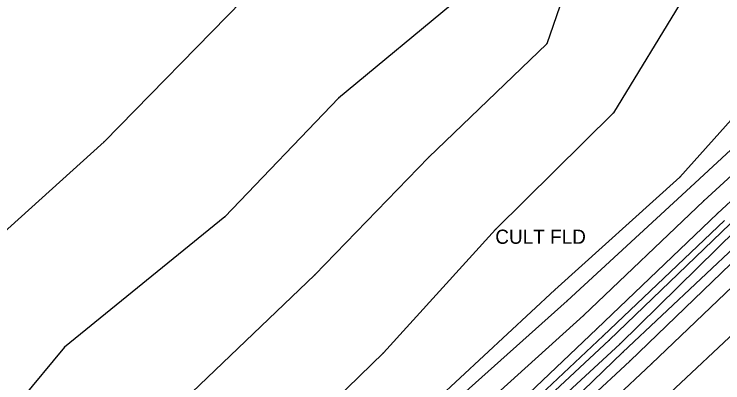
# Model space of a CAD drawing. Extents: x 1419505 to 1434054, y 1956910 to 1968644.
# Drawn here: x 1433605.5 to 1433855.4, y 1968338.4 to 1968468.2 of the extents above; entities that cross this region are included whole.
import ezdxf

# ---------------------------------------------------------------- set-up
doc = ezdxf.new("R2010")
doc.units = 0
for name, color, linetype in [('S_BREAKLINE', 7, 'Continuous'), ('S_DITCHLINE', 7, 'Continuous'), ('S_EDGE_PAVEMENT', 7, 'Continuous'), ('S_GRD_PT_SYM', 7, 'Continuous'), ('S_MSC_PT_SYM', 7, 'Continuous'), ('S_PAVEMENT_CROWN', 7, 'Continuous'), ('S_RDW_PT_SYM', 7, 'Continuous'), ('S_SHOULDER', 7, 'Continuous'), ('S_SURVEY_TEXT_ANNOT', 7, 'Continuous')]:
    doc.layers.add(name, color=color, linetype=linetype)

msp = doc.modelspace()

# ---------------------------------------------------------------- linework, layer by layer
at = {"layer": 'S_BREAKLINE'}
for p, q in [((1433813.2202, 1968515.1117), (1433793.2969, 1968457.802)), ((1433769.5064, 1968479.7105), (1433719.8082, 1968438.6018)), ((1433844.6113, 1968479.0114), (1433816.8765, 1968433.4835)), ((1433686.009, 1968473.093), (1433637.1959, 1968423.2958)), ((1433793.2969, 1968457.802), (1433751.5592, 1968417.7324)), ((1433870.993, 1968445.1822), (1433840.22, 1968410.773)), ((1433719.8082, 1968438.6018), (1433679.7596, 1968396.7851)), ((1433875.4372, 1968436.4227), (1433843.9742, 1968407.2728)), ((1433816.8765, 1968433.4835), (1433775.1918, 1968392.3258)), ((1433880.9386, 1968432.1494), (1433848.6865, 1968402.4875)), ((1433888.9011, 1968430.7533), (1433853.5108, 1968398.0462)), ((1433637.1959, 1968423.2958), (1433588.7407, 1968379.547)), ((1433751.5592, 1968417.7324), (1433711.5347, 1968376.4368)), ((1433840.22, 1968410.773), (1433796.2231, 1968371.1104)), ((1433843.9742, 1968407.2728), (1433800.5664, 1968367.2802)), ((1433848.6865, 1968402.4875), (1433806.3228, 1968362.0569)), ((1433679.7596, 1968396.7851), (1433623.2, 1968350.9581)), ((1433853.5108, 1968398.0462), (1433810.9331, 1968357.3636)), ((1433775.1918, 1968392.3258), (1433735.7682, 1968348.972)), ((1433860.1253, 1968392.2618), (1433819.0836, 1968352.0172)), ((1433862.7984, 1968389.2636), (1433820.1957, 1968349.097)), ((1433711.5347, 1968376.4368), (1433655.7821, 1968323.1873)), ((1433796.2231, 1968371.1104), (1433754.1524, 1968332.1799)), ((1433800.5664, 1968367.2802), (1433757.7176, 1968329.0797)), ((1433806.3228, 1968362.0569), (1433763.508, 1968323.4934)), ((1433810.9331, 1968357.3636), (1433769.0694, 1968317.559)), ((1433819.0836, 1968352.0172), (1433774.8767, 1968311.2866)), ((1433623.2, 1968350.9581), (1433583.6564, 1968303.4301)), ((1433735.7682, 1968348.972), (1433684.6589, 1968299.4658)), ((1433820.1957, 1968349.097), (1433777.9199, 1968308.5754))]:
    msp.add_line(p, q, dxfattribs=at)
at = {"layer": 'S_DITCHLINE'}
for p, q in [((1433855.973, 1968395.581), (1433813.2462, 1968354.9544)), ((1433858.0051, 1968394.3679), (1433815.3694, 1968353.3243)), ((1433813.2462, 1968354.9544), (1433771.0385, 1968315.3208)), ((1433815.3694, 1968353.3243), (1433773.3496, 1968314.4268))]:
    msp.add_line(p, q, dxfattribs=at)
at = {"layer": 'S_EDGE_PAVEMENT'}
for p, q in [((1433869.5289, 1968382.5402), (1433830.2483, 1968344.9908)), ((1433830.2483, 1968344.9908), (1433784.2344, 1968301.986))]:
    msp.add_line(p, q, dxfattribs=at)
at = {"layer": 'S_GRD_PT_SYM'}
for points in [[(1433793.2969, 1968457.802), (1433793.2969, 1968457.852), (1433793.2969, 1968457.802), (1433793.2469, 1968457.802), (1433793.2969, 1968457.802), (1433793.2969, 1968457.752), (1433793.2969, 1968457.802), (1433793.3469, 1968457.802)], [(1433719.8082, 1968438.6018), (1433719.8082, 1968438.6518), (1433719.8082, 1968438.6018), (1433719.7582, 1968438.6018), (1433719.8082, 1968438.6018), (1433719.8082, 1968438.5518), (1433719.8082, 1968438.6018), (1433719.8582, 1968438.6018)], [(1433816.8765, 1968433.4835), (1433816.8765, 1968433.5335), (1433816.8765, 1968433.4835), (1433816.8265, 1968433.4835), (1433816.8765, 1968433.4835), (1433816.8765, 1968433.4335), (1433816.8765, 1968433.4835), (1433816.9265, 1968433.4835)], [(1433637.1959, 1968423.2958), (1433637.1959, 1968423.3458), (1433637.1959, 1968423.2958), (1433637.1459, 1968423.2958), (1433637.1959, 1968423.2958), (1433637.1959, 1968423.2458), (1433637.1959, 1968423.2958), (1433637.2459, 1968423.2958)], [(1433751.5592, 1968417.7324), (1433751.5592, 1968417.7824), (1433751.5592, 1968417.7324), (1433751.5092, 1968417.7324), (1433751.5592, 1968417.7324), (1433751.5592, 1968417.6824), (1433751.5592, 1968417.7324), (1433751.6092, 1968417.7324)], [(1433840.22, 1968410.773), (1433840.22, 1968410.823), (1433840.22, 1968410.773), (1433840.17, 1968410.773), (1433840.22, 1968410.773), (1433840.22, 1968410.723), (1433840.22, 1968410.773), (1433840.27, 1968410.773)], [(1433843.9742, 1968407.2728), (1433843.9742, 1968407.3228), (1433843.9742, 1968407.2728), (1433843.9242, 1968407.2728), (1433843.9742, 1968407.2728), (1433843.9742, 1968407.2228), (1433843.9742, 1968407.2728), (1433844.0242, 1968407.2728)], [(1433848.6865, 1968402.4875), (1433848.6865, 1968402.5375), (1433848.6865, 1968402.4875), (1433848.6365, 1968402.4875), (1433848.6865, 1968402.4875), (1433848.6865, 1968402.4375), (1433848.6865, 1968402.4875), (1433848.7365, 1968402.4875)], [(1433679.7596, 1968396.7851), (1433679.7596, 1968396.8351), (1433679.7596, 1968396.7851), (1433679.7096, 1968396.7851), (1433679.7596, 1968396.7851), (1433679.7596, 1968396.7351), (1433679.7596, 1968396.7851), (1433679.8096, 1968396.7851)], [(1433853.5108, 1968398.0462), (1433853.5108, 1968398.0962), (1433853.5108, 1968398.0462), (1433853.4608, 1968398.0462), (1433853.5108, 1968398.0462), (1433853.5108, 1968397.9962), (1433853.5108, 1968398.0462), (1433853.5608, 1968398.0462)], [(1433775.1918, 1968392.3258), (1433775.1918, 1968392.3758), (1433775.1918, 1968392.3258), (1433775.1418, 1968392.3258), (1433775.1918, 1968392.3258), (1433775.1918, 1968392.2758), (1433775.1918, 1968392.3258), (1433775.2418, 1968392.3258)], [(1433711.5347, 1968376.4368), (1433711.5347, 1968376.4868), (1433711.5347, 1968376.4368), (1433711.4847, 1968376.4368), (1433711.5347, 1968376.4368), (1433711.5347, 1968376.3868), (1433711.5347, 1968376.4368), (1433711.5847, 1968376.4368)], [(1433796.2231, 1968371.1104), (1433796.2231, 1968371.1604), (1433796.2231, 1968371.1104), (1433796.1731, 1968371.1104), (1433796.2231, 1968371.1104), (1433796.2231, 1968371.0604), (1433796.2231, 1968371.1104), (1433796.2731, 1968371.1104)], [(1433800.5664, 1968367.2802), (1433800.5664, 1968367.3302), (1433800.5664, 1968367.2802), (1433800.5164, 1968367.2802), (1433800.5664, 1968367.2802), (1433800.5664, 1968367.2302), (1433800.5664, 1968367.2802), (1433800.6164, 1968367.2802)], [(1433806.3228, 1968362.0569), (1433806.3228, 1968362.1069), (1433806.3228, 1968362.0569), (1433806.2728, 1968362.0569), (1433806.3228, 1968362.0569), (1433806.3228, 1968362.0069), (1433806.3228, 1968362.0569), (1433806.3728, 1968362.0569)], [(1433810.9331, 1968357.3636), (1433810.9331, 1968357.4136), (1433810.9331, 1968357.3636), (1433810.8831, 1968357.3636), (1433810.9331, 1968357.3636), (1433810.9331, 1968357.3136), (1433810.9331, 1968357.3636), (1433810.9831, 1968357.3636)], [(1433813.2462, 1968354.9544), (1433813.2462, 1968355.0044), (1433813.2462, 1968354.9544), (1433813.1962, 1968354.9544), (1433813.2462, 1968354.9544), (1433813.2462, 1968354.9044), (1433813.2462, 1968354.9544), (1433813.2962, 1968354.9544)], [(1433815.3694, 1968353.3243), (1433815.3694, 1968353.3743), (1433815.3694, 1968353.3243), (1433815.3194, 1968353.3243), (1433815.3694, 1968353.3243), (1433815.3694, 1968353.2743), (1433815.3694, 1968353.3243), (1433815.4194, 1968353.3243)], [(1433819.0836, 1968352.0172), (1433819.0836, 1968352.0672), (1433819.0836, 1968352.0172), (1433819.0336, 1968352.0172), (1433819.0836, 1968352.0172), (1433819.0836, 1968351.9672), (1433819.0836, 1968352.0172), (1433819.1336, 1968352.0172)], [(1433623.2, 1968350.9581), (1433623.2, 1968351.0081), (1433623.2, 1968350.9581), (1433623.15, 1968350.9581), (1433623.2, 1968350.9581), (1433623.2, 1968350.9081), (1433623.2, 1968350.9581), (1433623.25, 1968350.9581)], [(1433735.7682, 1968348.972), (1433735.7682, 1968349.022), (1433735.7682, 1968348.972), (1433735.7182, 1968348.972), (1433735.7682, 1968348.972), (1433735.7682, 1968348.922), (1433735.7682, 1968348.972), (1433735.8182, 1968348.972)], [(1433820.1957, 1968349.097), (1433820.1957, 1968349.147), (1433820.1957, 1968349.097), (1433820.1457, 1968349.097), (1433820.1957, 1968349.097), (1433820.1957, 1968349.047), (1433820.1957, 1968349.097), (1433820.2457, 1968349.097)]]:
    msp.add_lwpolyline(points, dxfattribs=at)
at = {"layer": 'S_MSC_PT_SYM'}
msp.add_lwpolyline([(1433775.1718, 1968392.3198), (1433775.1718, 1968392.3698), (1433775.1718, 1968392.3198), (1433775.1218, 1968392.3198), (1433775.1718, 1968392.3198), (1433775.1718, 1968392.2698), (1433775.1718, 1968392.3198), (1433775.2218, 1968392.3198)], dxfattribs=at)
at = {"layer": 'S_PAVEMENT_CROWN'}
msp.add_line((1433879.1495, 1968374.4417), (1433836.7977, 1968334.7771), dxfattribs=at)
at = {"layer": 'S_RDW_PT_SYM'}
for points in [[(1433822.5838, 1968345.9928), (1433822.5838, 1968346.0428), (1433822.5838, 1968345.9928), (1433822.5338, 1968345.9928), (1433822.5838, 1968345.9928), (1433822.5838, 1968345.9428), (1433822.5838, 1968345.9928), (1433822.6338, 1968345.9928)], [(1433830.2483, 1968344.9908), (1433830.2483, 1968345.0408), (1433830.2483, 1968344.9908), (1433830.1983, 1968344.9908), (1433830.2483, 1968344.9908), (1433830.2483, 1968344.9408), (1433830.2483, 1968344.9908), (1433830.2983, 1968344.9908)]]:
    msp.add_lwpolyline(points, dxfattribs=at)
at = {"layer": 'S_SHOULDER'}
for p, q in [((1433865.1346, 1968386.9975), (1433822.5838, 1968345.9928)), ((1433822.5838, 1968345.9928), (1433780.2961, 1968306.8163))]:
    msp.add_line(p, q, dxfattribs=at)

# ---------------------------------------------------------------- texts
at = {"layer": 'S_SURVEY_TEXT_ANNOT'}
msp.add_text('CULT FLD', height=5, dxfattribs=at).set_placement((1433775.1718, 1968387.3198))

doc.saveas('drawing.dxf')
